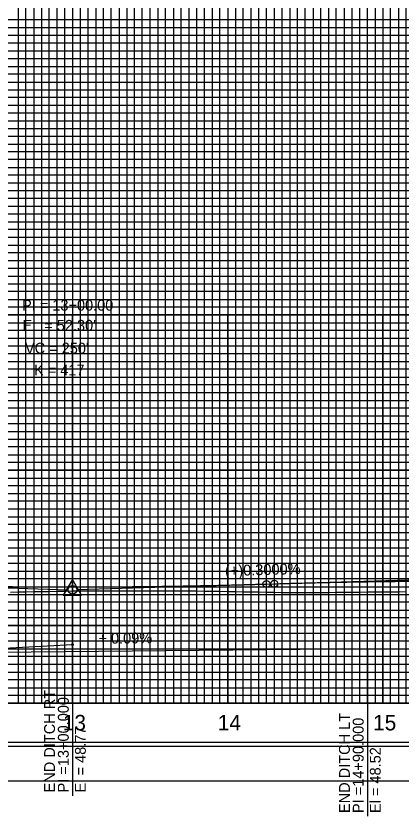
# Model space of a CAD drawing. Extents: x 2345490 to 2445302, y 465165 to 573888.
# Drawn here: x 2381944 to 2382192, y 536128 to 536643 of the extents above; entities that cross this region are included whole.
import ezdxf

# ---------------------------------------------------------------- set-up
doc = ezdxf.new("R2010")
doc.units = 0
for name, color, linetype in [('Old_Level_1', 7, 'Continuous'), ('Old_Level_18', 7, 'Continuous'), ('Old_Level_2', 7, 'Continuous'), ('Old_Level_3', 7, 'Continuous'), ('Old_Level_41', 7, 'Continuous'), ('Old_Level_42', 7, 'Continuous'), ('Old_Level_43', 7, 'Continuous'), ('Old_Level_50', 7, 'Continuous'), ('Old_Level_51', 7, 'Continuous'), ('Old_Level_57', 7, 'Continuous'), ('Old_Level_62', 7, 'Continuous'), ('Old_Level_63', 7, 'Continuous')]:
    doc.layers.add(name, color=color, linetype=linetype)

msp = doc.modelspace()

# ---------------------------------------------------------------- linework, layer by layer
at = {"layer": 'Old_Level_1'}
for points in [[(2381940.454, 536272.2225), (2381945.454, 536272.3225), (2381950.454, 536272.41925), (2381955.454, 536272.52), (2381960.454, 536272.62075), (2381965.454, 536272.7215), (2381970.454, 536272.82225), (2381975.454, 536272.923), (2381980.454, 536272.974), (2381985.454, 536272.97825), (2381990.454, 536272.98225), (2381995.454, 536272.9865), (2382000.454, 536272.991), (2382005.454, 536272.99525), (2382010.454, 536272.99925), (2382015.454, 536273.0035), (2382020.454, 536273.00775), (2382025.454, 536273.012), (2382030.454, 536273.01575), (2382035.454, 536273.02), (2382040.454, 536273.02425), (2382045.454, 536273.02825), (2382050.454, 536273.0325), (2382055.454, 536273.03675), (2382060.454, 536272.9915), (2382065.454, 536272.91325), (2382070.454, 536272.83325), (2382075.454, 536272.7525), (2382080.454, 536272.66425), (2382085.454, 536272.57575), (2382090.454, 536272.4875), (2382095.454, 536272.401), (2382100.454, 536272.313), (2382105.454, 536272.225), (2382110.454, 536272.13725), (2382115.454, 536272.04925), (2382120.454, 536271.96125), (2382125.454, 536271.88175), (2382130.454, 536271.9275), (2382135.454, 536271.97325), (2382140.454, 536272.019), (2382145.454, 536272.06475), (2382150.454, 536272.11025), (2382155.454, 536272.156), (2382160.454, 536272.20175), (2382165.454, 536272.251), (2382170.454, 536272.29675), (2382175.454, 536272.3425), (2382180.454, 536272.388)], [(2382180.454, 536272.388), (2382185.454, 536272.43375), (2382190.454, 536272.47925), (2382195.454, 536272.52875)]]:
    msp.add_lwpolyline(points, dxfattribs=at)
at = {"layer": 'Old_Level_18'}
msp.add_lwpolyline([(2383130.454, 537225.68175), (2381630.454, 537225.68175), (2381630.454, 536175.68175), (2383130.454, 536175.68175)], close=True, dxfattribs=at)
at = {"layer": 'Old_Level_2'}
for p, q in [((2382110.454, 536277.58175), (2382227.70525, 536281.09925)), ((2381855.454, 536277.43175), (2381977.70525, 536273.764)), ((2382105.454, 536277.43175), (2381983.203, 536273.764)), ((2382105.454, 536277.43175), (2382110.454, 536277.58175))]:
    msp.add_line(p, q, dxfattribs=at)
msp.add_lwpolyline([(2381974.49925, 536270.25925), (2381986.24175, 536270.25925), (2381980.37075, 536280.385)], close=True, dxfattribs=at)
for centre, radius in [((2382105.454, 536277.43175), 2.25), ((2382110.454, 536277.58175), 2.25), ((2381980.454, 536273.68175), 2.75)]:
    msp.add_circle(centre, radius, dxfattribs=at)
for points in [[(2382110.454, 536277.58175), (2382115.254, 536277.72275), (2382120.054, 536277.858), (2382124.854, 536277.98775), (2382129.654, 536278.1115), (2382134.454, 536278.22975), (2382139.254, 536278.342), (2382144.054, 536278.4485), (2382148.854, 536278.54925), (2382153.654, 536278.64425), (2382158.454, 536278.73375), (2382163.254, 536278.81725), (2382168.054, 536278.895), (2382172.854, 536278.967), (2382177.654, 536279.03325), (2382182.454, 536279.09375), (2382187.254, 536279.14825), (2382192.054, 536279.19725), (2382196.854, 536279.2405), (2382201.654, 536279.278), (2382206.454, 536279.30975), (2382211.254, 536279.3355), (2382216.054, 536279.35575), (2382220.854, 536279.37), (2382225.654, 536279.37875), (2382230.454, 536279.38175), (2382235.254, 536279.37875), (2382240.054, 536279.37), (2382244.854, 536279.35575), (2382249.654, 536279.3355), (2382254.454, 536279.30975), (2382259.254, 536279.278), (2382264.054, 536279.2405), (2382268.854, 536279.19725), (2382273.654, 536279.14825), (2382278.454, 536279.09375), (2382283.254, 536279.03325), (2382288.054, 536278.967), (2382292.854, 536278.895), (2382297.654, 536278.81725), (2382302.454, 536278.73375), (2382307.254, 536278.64425), (2382312.054, 536278.54925), (2382316.854, 536278.4485), (2382321.654, 536278.342), (2382326.454, 536278.22975), (2382331.254, 536278.1115), (2382336.054, 536277.98775), (2382340.854, 536277.858), (2382345.654, 536277.72275), (2382350.454, 536277.58175)], [(2381855.454, 536277.43175), (2381860.454, 536277.28475), (2381865.454, 536277.14375), (2381870.454, 536277.00875), (2381875.454, 536276.87975), (2381880.454, 536276.75675), (2381885.454, 536276.63975), (2381890.454, 536276.52875), (2381895.454, 536276.42375), (2381900.454, 536276.32475), (2381905.454, 536276.23175), (2381910.454, 536276.14475), (2381915.454, 536276.06375), (2381920.454, 536275.98875), (2381925.454, 536275.91975), (2381930.454, 536275.85675), (2381935.454, 536275.79975), (2381940.454, 536275.74875), (2381945.454, 536275.70375), (2381950.454, 536275.66475), (2381955.454, 536275.63175), (2381960.454, 536275.60475), (2381965.454, 536275.58375), (2381970.454, 536275.56875), (2381975.454, 536275.55975), (2381980.454, 536275.55675), (2381985.454, 536275.55975), (2381990.454, 536275.56875), (2381995.454, 536275.58375), (2382000.454, 536275.60475), (2382005.454, 536275.63175), (2382010.454, 536275.66475), (2382015.454, 536275.70375), (2382020.454, 536275.74875), (2382025.454, 536275.79975), (2382030.454, 536275.85675), (2382035.454, 536275.91975), (2382040.454, 536275.98875), (2382045.454, 536276.06375), (2382050.454, 536276.14475), (2382055.454, 536276.23175), (2382060.454, 536276.32475), (2382065.454, 536276.42375), (2382070.454, 536276.52875), (2382075.454, 536276.63975), (2382080.454, 536276.75675), (2382085.454, 536276.87975), (2382090.454, 536277.00875), (2382095.454, 536277.14375), (2382100.454, 536277.28475), (2382105.454, 536277.43175)]]:
    msp.add_spline(points, degree=3, dxfattribs=at)
at = {"layer": 'Old_Level_3'}
for p, q in [((2381830.454, 536230.68175), (2381980.454, 536238.38175)), ((2381980.454, 536238.38175), (2381980.454, 536141.03096)), ((2381830.454, 536232.68175), (2382170.454, 536235.88175)), ((2382170.454, 536235.88175), (2382170.454, 536128.05924))]:
    msp.add_line(p, q, dxfattribs=at)
msp.add_circle((2381980.454, 536238.38175), 0.5, dxfattribs=at)
at = {"layer": 'Old_Level_41'}
msp.add_line((2383130.454, 536200.68175), (2381630.454, 536200.68175), dxfattribs=at)
for points in [[(2381630.454, 537225.68175), (2381680.454, 537225.68175), (2381680.454, 536200.68175), (2381730.454, 536200.68175), (2381730.454, 537225.68175), (2381780.454, 537225.68175), (2381780.454, 536200.68175), (2381830.454, 536200.68175), (2381830.454, 537225.68175), (2381880.454, 537225.68175), (2381880.454, 536200.68175), (2381930.454, 536200.68175), (2381930.454, 537225.68175), (2381980.454, 537225.68175), (2381980.454, 536200.68175), (2382030.454, 536200.68175), (2382030.454, 537225.68175), (2382080.454, 537225.68175), (2382080.454, 536200.68175), (2382130.454, 536200.68175), (2382130.454, 537225.68175), (2382180.454, 537225.68175), (2382180.454, 536200.68175), (2382230.454, 536200.68175)], [(2381705.454, 536200.68175), (2381705.454, 537225.68175), (2381755.454, 537225.68175), (2381755.454, 536200.68175), (2381805.454, 536200.68175), (2381805.454, 537225.68175), (2381855.454, 537225.68175), (2381855.454, 536200.68175), (2381905.454, 536200.68175), (2381905.454, 537225.68175), (2381955.454, 537225.68175), (2381955.454, 536200.68175), (2382005.454, 536200.68175), (2382005.454, 537225.68175), (2382055.454, 537225.68175), (2382055.454, 536200.68175), (2382105.454, 536200.68175), (2382105.454, 537225.68175), (2382155.454, 537225.68175), (2382155.454, 536200.68175), (2382205.454, 536200.68175)], [(2383130.454, 536625.68175), (2381630.454, 536625.68175), (2381630.454, 536575.68175), (2383130.454, 536575.68175)], [(2383130.454, 536550.68175), (2381630.454, 536550.68175), (2381630.454, 536600.68175), (2383130.454, 536600.68175)], [(2383130.454, 536525.68175), (2381630.454, 536525.68175), (2381630.454, 536475.68175), (2383130.454, 536475.68175)], [(2383130.454, 536450.68175), (2381630.454, 536450.68175), (2381630.454, 536500.68175), (2383130.454, 536500.68175)], [(2383130.454, 536425.68175), (2381630.454, 536425.68175), (2381630.454, 536375.68175), (2383130.454, 536375.68175)], [(2383130.454, 536325.68175), (2381630.454, 536325.68175), (2381630.454, 536275.68175), (2383130.454, 536275.68175)], [(2383130.454, 536250.68175), (2381630.454, 536250.68175), (2381630.454, 536300.68175), (2383130.454, 536300.68175)], [(2383130.454, 536225.68175), (2381630.454, 536225.68175)]]:
    msp.add_lwpolyline(points, dxfattribs=at)
at = {"layer": 'Old_Level_42'}
msp.add_lwpolyline([(2383130.454, 536350.68175), (2381630.454, 536350.68175), (2381630.454, 536400.68175), (2383130.454, 536400.68175)], dxfattribs=at)
at = {"layer": 'Old_Level_43'}
for points in [[(2381945.454, 537225.68175), (2381945.454, 536200.68175), (2381950.454, 536200.68175), (2381950.454, 537225.68175)], [(2381960.454, 537225.68175), (2381960.454, 536200.68175), (2381965.454, 536200.68175), (2381965.454, 537225.68175)], [(2381970.454, 537225.68175), (2381970.454, 536200.68175), (2381975.454, 536200.68175), (2381975.454, 537225.68175)], [(2381985.454, 537225.68175), (2381985.454, 536200.68175), (2381990.454, 536200.68175), (2381990.454, 537225.68175)], [(2381995.454, 537225.68175), (2381995.454, 536200.68175), (2382000.454, 536200.68175), (2382000.454, 537225.68175)], [(2382010.454, 537225.68175), (2382010.454, 536200.68175), (2382025.454, 536200.68175), (2382025.454, 537225.68175)], [(2382015.454, 537225.68175), (2382015.454, 536200.68175), (2382020.454, 536200.68175), (2382020.454, 537225.68175)], [(2382015.454, 537225.08175), (2382015.454, 536200.68175), (2382020.454, 536200.68175), (2382020.454, 537225.08175)], [(2382035.454, 537225.68175), (2382035.454, 536200.68175), (2382040.454, 536200.68175), (2382040.454, 537225.68175)], [(2382045.454, 537225.68175), (2382045.454, 536200.68175), (2382050.454, 536200.68175), (2382050.454, 537225.68175)], [(2382060.454, 537225.68175), (2382060.454, 536200.68175), (2382065.454, 536200.68175), (2382065.454, 537225.68175)], [(2382070.454, 537225.68175), (2382070.454, 536200.68175), (2382075.454, 536200.68175), (2382075.454, 537225.68175)], [(2382085.454, 537225.68175), (2382085.454, 536200.68175), (2382090.454, 536200.68175), (2382090.454, 537225.68175)], [(2382095.454, 537225.68175), (2382095.454, 536200.68175), (2382100.454, 536200.68175), (2382100.454, 537225.68175)], [(2382110.454, 537225.68175), (2382110.454, 536200.68175), (2382115.454, 536200.68175), (2382115.454, 537225.68175)], [(2382120.454, 537225.68175), (2382120.454, 536200.68175), (2382125.454, 536200.68175), (2382125.454, 537225.68175)], [(2382135.454, 537225.68175), (2382135.454, 536200.68175), (2382140.454, 536200.68175), (2382140.454, 537225.68175)], [(2382145.454, 537225.68175), (2382145.454, 536200.68175), (2382150.454, 536200.68175), (2382150.454, 537225.68175)], [(2382160.454, 537225.68175), (2382160.454, 536200.68175)], [(2382165.454, 537225.68175), (2382165.454, 536200.68175), (2382170.454, 536200.68175), (2382170.454, 537225.68175), (2382175.454, 537225.68175), (2382175.454, 536200.68175), (2382185.454, 536200.68175), (2382185.454, 537225.68175), (2382190.454, 537225.68175), (2382190.454, 536200.68175), (2382195.454, 536200.68175), (2382195.454, 537225.68175), (2382200.454, 537225.68175), (2382200.454, 536200.68175)], [(2383080.454, 536640.68175), (2381680.454, 536640.68175), (2381680.454, 536635.68175), (2383080.454, 536635.68175)], [(2383080.454, 536630.68175), (2381680.454, 536630.68175), (2381680.454, 536620.68175), (2383080.454, 536620.68175)], [(2383080.454, 536615.68175), (2381680.454, 536615.68175), (2381680.454, 536610.68175), (2383080.454, 536610.68175)], [(2383080.454, 536605.68175), (2381680.454, 536605.68175), (2381680.454, 536595.68175), (2383080.454, 536595.68175)], [(2383080.454, 536590.68175), (2381680.454, 536590.68175), (2381680.454, 536585.68175), (2383080.454, 536585.68175)], [(2383080.454, 536580.68175), (2381680.454, 536580.68175), (2381680.454, 536570.68175), (2383080.454, 536570.68175)], [(2383080.454, 536565.68175), (2381680.454, 536565.68175), (2381680.454, 536560.68175), (2383080.454, 536560.68175)], [(2383080.454, 536555.68175), (2381680.454, 536555.68175), (2381680.454, 536545.68175), (2383080.454, 536545.68175)], [(2383080.454, 536540.68175), (2381680.454, 536540.68175), (2381680.454, 536535.68175), (2383080.454, 536535.68175)], [(2383080.454, 536530.68175), (2381680.454, 536530.68175), (2381680.454, 536520.68175), (2383080.454, 536520.68175)], [(2383080.454, 536515.68175), (2381680.454, 536515.68175), (2381680.454, 536510.68175), (2383080.454, 536510.68175)], [(2383080.454, 536505.68175), (2381680.454, 536505.68175), (2381680.454, 536495.68175), (2383080.454, 536495.68175)], [(2383080.454, 536490.68175), (2381680.454, 536490.68175), (2381680.454, 536485.68175), (2383080.454, 536485.68175)], [(2383080.454, 536480.68175), (2381680.454, 536480.68175), (2381680.454, 536470.68175), (2383080.454, 536470.68175)], [(2383080.454, 536465.68175), (2381680.454, 536465.68175), (2381680.454, 536460.68175), (2383080.454, 536460.68175)], [(2383080.454, 536455.68175), (2381680.454, 536455.68175), (2381680.454, 536445.68175), (2383080.454, 536445.68175)], [(2383080.454, 536440.68175), (2381680.454, 536440.68175), (2381680.454, 536435.68175), (2383080.454, 536435.68175)], [(2383080.454, 536430.68175), (2381680.454, 536430.68175), (2381680.454, 536420.68175), (2383080.454, 536420.68175)], [(2383080.454, 536415.68175), (2381680.454, 536415.68175), (2381680.454, 536410.68175), (2383080.454, 536410.68175)], [(2383080.454, 536405.68175), (2381680.454, 536405.68175)], [(2381680.454, 536395.68175), (2383080.454, 536395.68175)], [(2383080.454, 536390.68175), (2381680.454, 536390.68175), (2381680.454, 536385.68175), (2383080.454, 536385.68175)], [(2383080.454, 536380.68175), (2381680.454, 536380.68175)], [(2381680.454, 536370.68175), (2383080.454, 536370.68175)], [(2383080.454, 536365.68175), (2381680.454, 536365.68175), (2381680.454, 536360.68175), (2383080.454, 536360.68175)], [(2383080.454, 536355.68175), (2381680.454, 536355.68175), (2381680.454, 536345.68175), (2383080.454, 536345.68175)], [(2383080.454, 536340.68175), (2381680.454, 536340.68175), (2381680.454, 536335.68175), (2383080.454, 536335.68175)], [(2383080.454, 536330.68175), (2381680.454, 536330.68175), (2381680.454, 536320.68175), (2383080.454, 536320.68175)], [(2383080.454, 536315.68175), (2381680.454, 536315.68175), (2381680.454, 536310.68175), (2383080.454, 536310.68175)], [(2383080.454, 536305.68175), (2381680.454, 536305.68175), (2381680.454, 536295.68175), (2383080.454, 536295.68175)], [(2383080.454, 536290.68175), (2381680.454, 536290.68175), (2381680.454, 536285.68175), (2383080.454, 536285.68175)], [(2383080.454, 536280.68175), (2381680.454, 536280.68175), (2381680.454, 536270.68175), (2383080.454, 536270.68175)], [(2383080.454, 536265.68175), (2381680.454, 536265.68175), (2381680.454, 536260.68175), (2383080.454, 536260.68175)], [(2383080.454, 536255.68175), (2381680.454, 536255.68175), (2381680.454, 536245.68175), (2383080.454, 536245.68175)], [(2383080.454, 536240.68175), (2381680.454, 536240.68175), (2381680.454, 536235.68175), (2383080.454, 536235.68175)], [(2383080.454, 536230.68175), (2381680.454, 536230.68175), (2381680.454, 536220.68175), (2383080.454, 536220.68175)], [(2383080.454, 536215.68175), (2381680.454, 536215.68175), (2381680.454, 536210.68175), (2383080.454, 536210.68175)], [(2383080.454, 536205.68175), (2381680.454, 536205.68175)]]:
    msp.add_lwpolyline(points, dxfattribs=at)
at = {"layer": 'Old_Level_50'}
msp.add_lwpolyline([(2383142.954, 537228.23175), (2381476.454, 537228.23175), (2381476.454, 536173.13175), (2383142.954, 536173.13175)], close=True, dxfattribs=at)
at = {"layer": 'Old_Level_51'}
msp.add_lwpolyline([(2383147.454, 537250.68175), (2381463.454, 537250.68175), (2381463.454, 536150.68175), (2383147.454, 536150.68175)], close=True, dxfattribs=at)
at = {"layer": 'Old_Level_57'}
for p, q in [((2381630.45425, 536450.682), (2383880.45375, 536450.682)), ((2381980.45375, 536200.682), (2381980.45375, 536450.682)), ((2382080.45375, 536200.682), (2382080.45375, 536450.682)), ((2382080.45375, 536200.782), (2382080.45375, 536450.682)), ((2382180.45375, 536200.682), (2382180.45375, 536450.682)), ((2382180.45375, 536200.782), (2382180.45375, 536450.682)), ((2381630.45425, 536400.682), (2383880.45375, 536400.682)), ((2381630.45425, 536350.682), (2383880.45375, 536350.682)), ((2381630.45425, 536300.682), (2383880.45375, 536300.682)), ((2381630.454, 536250.682), (2383880.45375, 536250.682)), ((2381630.45425, 536200.682), (2383880.45375, 536200.682))]:
    msp.add_line(p, q, dxfattribs=at)
at = {"layer": 'Old_Level_63'}
msp.add_line((2381680.454, 536200.68175), (2383096.698, 536200.68175), dxfattribs=at)

# ---------------------------------------------------------------- texts
at = {"layer": 'Old_Level_2'}
for s, height, p in [('PI = 13+00.00', 7.0000005, (2381947.96225, 536453.46409)), ("EL = 52.30'", 7.0000005, (2381948.23325, 536440.48959)), ("VC = 250'", 7.000001, (2381949.85025, 536425.78934)), ('K = 417', 7.000001, (2381955.69175, 536411.76484))]:
    msp.add_text(s, height=height, dxfattribs=at).set_placement(p)
msp.add_text('(+)0.3000%', height=7.000001, rotation=1.7183583, dxfattribs=at).set_placement((2382078.8505, 536282.4704))
at = {"layer": 'Old_Level_3'}
for s, height, rotation, p in [('+ 0.09%', 7.000001, 0.5392, (2381997.22429, 536238.95062)), ('END DITCH RT', 7.0000005, 90, (2381969.1751, 536143.242)), ('PI =13+00.000', 7.0000005, 90, (2381978.049, 536143.242)), ('END DITCH LT', 7.0000005, 90, (2382159.1751, 536129.9615)), ('PI =14+90.000', 7.0000005, 90, (2382168.049, 536129.9615)), ('El = 48.77', 7.000001, 90, (2381989.049, 536143.242)), ('El = 48.52', 7.000001, 90, (2382179.049, 536129.9615))]:
    msp.add_text(s, height=height, rotation=rotation, dxfattribs=at).set_placement(p)
at = {"layer": 'Old_Level_62'}
for s, p in [('13', (2381974.26, 536183.18175)), ('14', (2382074.1025, 536183.18175)), ('15', (2382174.195, 536183.18175))]:
    msp.add_text(s, height=10.000001, dxfattribs=at).set_placement(p)

doc.saveas('drawing.dxf')
